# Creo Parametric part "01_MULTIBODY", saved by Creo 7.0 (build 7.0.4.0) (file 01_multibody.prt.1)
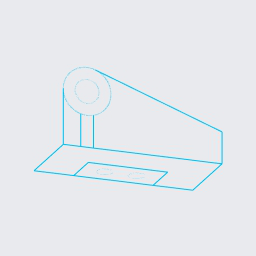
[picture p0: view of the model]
Units: millimeter Kilogram Sec (mmKs); MM, KILOGRAM, SECS
Materials in the file: S235JRG2

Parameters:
  PTC_MATERIAL_NAME = "S235JRG2"
  BENENNUNG = "XXX"
  DATUM = "XX.XX.XX"
  ERSTELLER = "ARINDA"
  TEILETYP = "Fertigungsteil"
  SELECT_EN_NAME = "S235JRG2"
  SELECT_DIN_NAME = "RSt37-2"
  SELECT_DIN_NUMBER = "1.0038"
  SELECT_ASTM_NAME = "A 283 M Grade 2"
  MATERIAL_GROUP = "ME_ST_Baustahl"
  STANDARD_EN_DELIVERYSPEC = "DIN EN 10025"
  STANDARD_DIN_DELIVERYSPEC = "DIN 17100"

Other parameters: MASSE

Created from: ARINDA-STARTTEIL.PRT

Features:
  1. coordinate system "CS0"
  2. datum plane "DTM1", "T_RECHTS_Y-Z"
  3. datum plane "DTM2", "T_OBEN_X-Z"
  4. datum plane "DTM3", "T_VORNE_X-Y"
  5. datum axis "T_X-ACHSE"
  6. datum axis "A_1"
  7. datum axis "A_2"
  8. sketch "Skizze 1"
  9. sketch "Skizze 2"

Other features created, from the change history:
  sketch "Skizze 2"

Other named items: T_BASIC, T_Y-ACHSE, T_Z-ACHSE

Layers: 00_STD-ACHSEN, 00_STD-EBENEN, 00_STD-KOORDSYS, 01_KURVEN, KURVENELEMENTE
